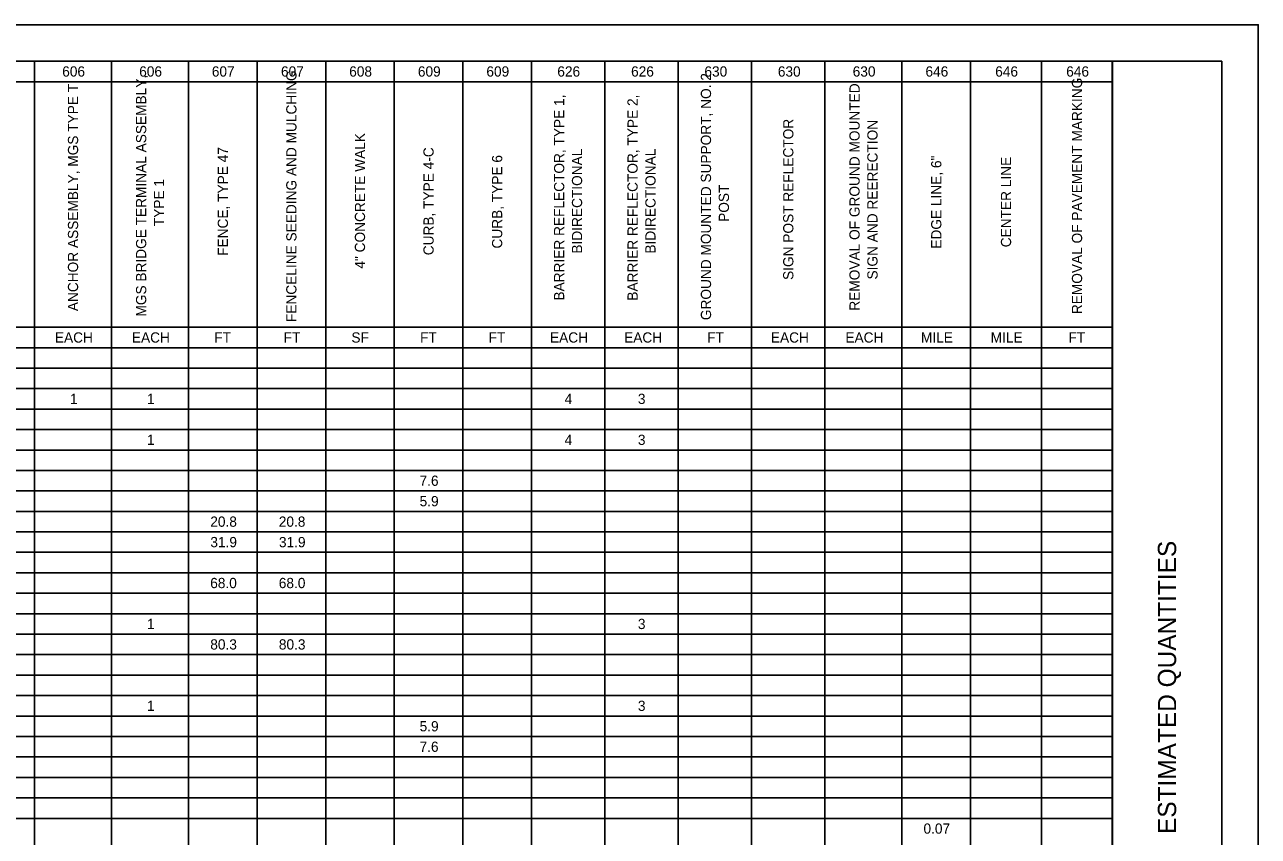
# Model space of a CAD drawing. Extents: x 0 to 34, y 0 to 22.
# Drawn here: x 17.11 to 34, y 10.89 to 22 of the extents above; entities that cross this region are included whole.
import ezdxf

# ---------------------------------------------------------------- set-up
doc = ezdxf.new("R2010")
doc.units = 0
for name, color, linetype in [('SH_Border', 7, 'Continuous'), ('SH_Cut_Line', 7, 'Continuous'), ('SH_Data', 7, 'Continuous'), ('SH_Text', 7, 'Continuous')]:
    doc.layers.add(name, color=color, linetype=linetype)

msp = doc.modelspace()

# ---------------------------------------------------------------- linework, layer by layer
at = {"layer": 'SH_Border'}
msp.add_line((32, 0.5), (32, 21.5), dxfattribs=at)
msp.add_lwpolyline([(1.5, 21.5), (33.5, 21.5), (33.5, 0.5), (1.5, 0.5)], close=True, dxfattribs=at)
at = {"layer": 'SH_Cut_Line'}
msp.add_lwpolyline([(0, 0), (34, 0), (34, 22), (0, 22)], close=True, dxfattribs=at)
at = {"layer": 'SH_Data'}
for p, q in [((1.5, 21.5), (32.004, 21.5)), ((17.246, 21.5), (17.246, 0.5)), ((18.3, 21.5), (18.3, 0.5)), ((19.354, 21.5), (19.354, 0.5)), ((20.293, 21.5), (20.293, 0.5)), ((21.232, 21.5), (21.232, 0.5)), ((22.171, 21.5), (22.171, 0.5)), ((23.109, 21.5), (23.109, 0.5)), ((24.048, 21.5), (24.048, 0.5)), ((25.053, 21.5), (25.053, 0.5)), ((26.058, 21.5), (26.058, 0.5)), ((27.062, 21.5), (27.062, 0.5)), ((28.067, 21.5), (28.067, 0.5)), ((29.121, 21.5), (29.121, 0.5)), ((30.06, 21.5), (30.06, 0.5)), ((31.032, 21.5), (31.032, 0.5)), ((32.004, 21.5), (32.004, 0.5)), ((8.813, 21.22), (32.004, 21.22)), ((8.813, 17.86), (32.004, 17.86)), ((1.5, 17.58), (32.004, 17.58)), ((1.5, 17.3), (32.004, 17.3)), ((1.5, 17.02), (32.004, 17.02)), ((1.5, 16.74), (32.004, 16.74)), ((1.5, 16.46), (32.004, 16.46)), ((1.5, 16.18), (32.004, 16.18)), ((1.5, 15.9), (32.004, 15.9)), ((1.5, 15.62), (32.004, 15.62)), ((1.5, 15.34), (32.004, 15.34)), ((1.5, 15.06), (32.004, 15.06)), ((1.5, 14.78), (32.004, 14.78)), ((1.5, 14.5), (32.004, 14.5)), ((1.5, 14.22), (32.004, 14.22)), ((1.5, 13.94), (32.004, 13.94)), ((1.5, 13.66), (32.004, 13.66)), ((1.5, 13.38), (32.004, 13.38)), ((1.5, 13.1), (32.004, 13.1)), ((1.5, 12.82), (32.004, 12.82)), ((1.5, 12.54), (32.004, 12.54)), ((1.5, 12.26), (32.004, 12.26)), ((1.5, 11.98), (32.004, 11.98)), ((1.5, 11.7), (32.004, 11.7)), ((1.5, 11.42), (32.004, 11.42)), ((1.5, 11.14), (32.004, 11.14))]:
    msp.add_line(p, q, dxfattribs=at)

# ---------------------------------------------------------------- texts
msp.add_text('ESTIMATED QUANTITIES', height=0.25, rotation=90, dxfattribs=at).set_placement((32.875, 10.926))
at = {"layer": 'SH_Text'}
for s, p in [('606', (17.625, 21.29)), ('606', (18.679, 21.29)), ('607', (19.673, 21.29)), ('607', (20.62, 21.29)), ('608', (21.554, 21.29)), ('609', (22.494, 21.29)), ('609', (23.432, 21.29)), ('626', (24.403, 21.29)), ('626', (25.413, 21.29)), ('630', (26.417, 21.29)), ('630', (27.422, 21.29)), ('630', (28.447, 21.29)), ('646', (29.443, 21.29)), ('646', (30.398, 21.29)), ('646', (31.37, 21.29)), ('EACH', (17.525, 17.65)), ('EACH', (18.579, 17.65)), ('FT', (19.707, 17.65)), ('FT', (20.657, 17.65)), ('SF', (21.584, 17.65)), ('FT', (22.524, 17.65)), ('FT', (23.463, 17.65)), ('EACH', (24.303, 17.65)), ('EACH', (25.318, 17.65)), ('FT', (26.454, 17.65)), ('EACH', (27.327, 17.65)), ('EACH', (28.347, 17.65)), ('MILE', (29.381, 17.65)), ('MILE', (30.336, 17.65)), ('FT', (31.401, 17.65)), ('1', (17.731, 16.81)), ('1', (18.785, 16.81)), ('4', (24.503, 16.81)), ('3', (25.506, 16.81)), ('1', (18.785, 16.25)), ('4', (24.503, 16.25)), ('3', (25.506, 16.25)), ('7.6', (22.517, 15.69)), ('5.9', (22.518, 15.41)), ('20.8', (19.652, 15.13)), ('20.8', (20.59, 15.13)), ('31.9', (19.653, 14.85)), ('31.9', (20.592, 14.85)), ('68.0', (19.651, 14.29)), ('68.0', (20.59, 14.29)), ('1', (18.785, 13.73)), ('3', (25.506, 13.73)), ('80.3', (19.652, 13.45)), ('80.3', (20.591, 13.45)), ('1', (18.785, 12.61)), ('3', (25.506, 12.61)), ('5.9', (22.518, 12.33)), ('7.6', (22.517, 12.05)), ('0.07', (29.416, 10.93))]:
    msp.add_text(s, height=0.14, dxfattribs=at).set_placement(p)
for s, p in [('MGS BRIDGE TERMINAL ASSEMBLY, ', (18.775, 18.006)), ('FENCELINE SEEDING AND MULCHING', (20.832, 17.931)), ('GROUND MOUNTED SUPPORT, NO. 2 ', (26.508, 17.957)), ('ANCHOR ASSEMBLY, MGS TYPE T', (17.843, 18.08)), ('REMOVAL OF GROUND MOUNTED ', (28.542, 18.087)), ('REMOVAL OF PAVEMENT MARKING', (31.588, 18.039)), ('BARRIER REFLECTOR, TYPE 1, ', (24.498, 18.225)), ('BARRIER REFLECTOR, TYPE 2, ', (25.503, 18.224)), ('SIGN POST REFLECTOR', (27.635, 18.507)), ('SIGN AND REERECTION', (28.787, 18.513)), ('4" CONCRETE WALK', (21.771, 18.662)), ('FENCE, TYPE 47', (19.894, 18.837)), ('CURB, TYPE 4-C', (22.71, 18.845)), ('BIDIRECTIONAL', (24.743, 18.868)), ('BIDIRECTIONAL', (25.748, 18.868)), ('CURB, TYPE 6', (23.649, 18.937)), ('EDGE LINE, 6"', (29.661, 18.935)), ('CENTER LINE', (30.616, 18.954)), ('TYPE 1', (19.02, 19.243)), ('POST', (26.753, 19.302))]:
    msp.add_text(s, height=0.14, rotation=90, dxfattribs=at).set_placement(p)

doc.saveas('drawing.dxf')
